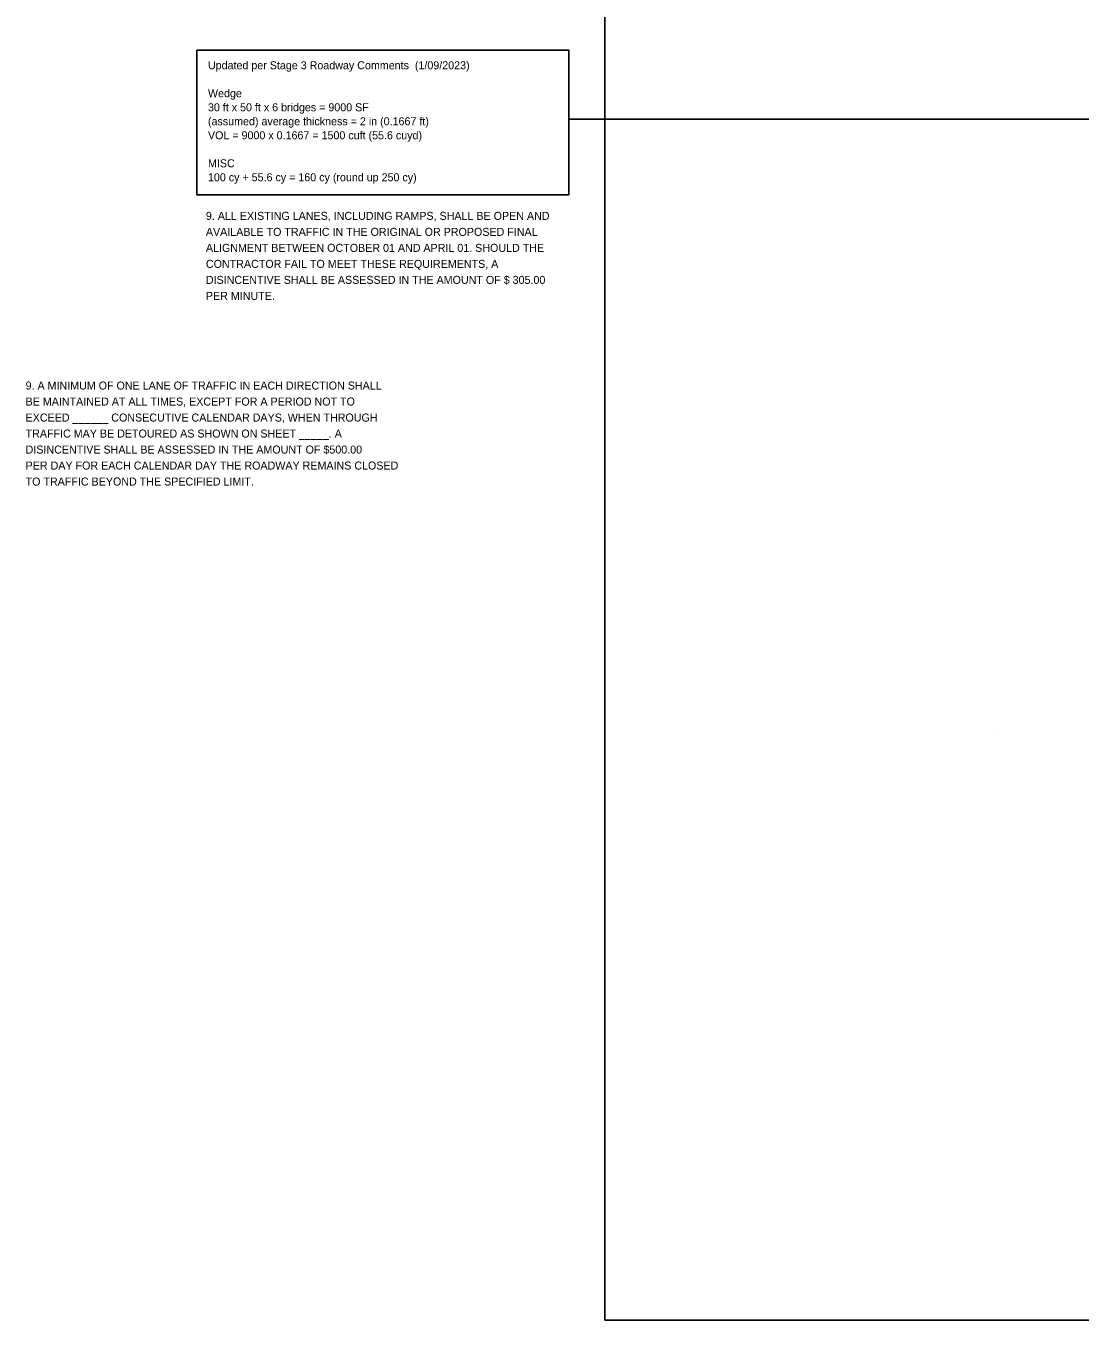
# Model space of a CAD drawing. Extents: x 1820207 to 1820557, y 740216 to 740315.
# Drawn here: x 1820207.07 to 1820225.52, y 740244.01 to 740266.65 of the extents above; entities that cross this region are included whole.
import ezdxf

# ---------------------------------------------------------------- set-up
doc = ezdxf.new("R2010")
doc.units = 0
for name, color, linetype in [('SC_Scratch1', 7, 'Continuous'), ('SC_Shading1', 7, 'Continuous'), ('SH_Text', 7, 'Continuous')]:
    doc.layers.add(name, color=color, linetype=linetype)

msp = doc.modelspace()

# ---------------------------------------------------------------- linework, layer by layer
at = {"layer": 'SC_Scratch1'}
msp.add_line((1820224.047, 740254.242), (1820224.047, 740254.242), dxfattribs=at)
at = {"layer": 'SC_Shading1'}
msp.add_line((1820225.997, 740265.022), (1820216.573, 740265.022), dxfattribs=at)
msp.add_lwpolyline([(1820210.061, 740266.228), (1820216.573, 740266.228), (1820216.573, 740263.7), (1820210.061, 740263.7)], close=True, dxfattribs=at)
at = {"layer": 'SH_Text'}
msp.add_lwpolyline([(1820217.201, 740244.009), (1820515.724, 740244.009), (1820515.724, 740286.62), (1820217.201, 740286.62)], close=True, dxfattribs=at)

# ---------------------------------------------------------------- texts
at = {"layer": 'SC_Shading1'}
for s, p in [('Updated per Stage 3 Roadway Comments  (1/09/2023)', (1820210.257, 740265.895)), ('Wedge', (1820210.257, 740265.405)), ('30 ft x 50 ft x 6 bridges = 9000 SF', (1820210.257, 740265.16)), ('(assumed) average thickness = 2 in (0.1667 ft)', (1820210.257, 740264.915)), ('VOL = 9000 x 0.1667 = 1500 cuft (55.6 cuyd)', (1820210.257, 740264.67)), ('MISC', (1820210.257, 740264.18)), ('100 cy + 55.6 cy = 160 cy (round up 250 cy)', (1820210.257, 740263.935))]:
    msp.add_text(s, height=0.14, dxfattribs=at).set_placement(p)
at = {"layer": 'SH_Text'}
for s, p in [('9. ALL EXISTING LANES, INCLUDING RAMPS, SHALL BE OPEN AND ', (1820210.221, 740263.26)), ('AVAILABLE TO TRAFFIC IN THE ORIGINAL OR PROPOSED FINAL ', (1820210.221, 740262.98)), ('ALIGNMENT BETWEEN OCTOBER 01 AND APRIL 01. SHOULD THE ', (1820210.221, 740262.7)), ('CONTRACTOR FAIL TO MEET THESE REQUIREMENTS, A ', (1820210.221, 740262.42)), ('DISINCENTIVE SHALL BE ASSESSED IN THE AMOUNT OF $ 305.00 ', (1820210.221, 740262.14)), ('PER MINUTE.', (1820210.221, 740261.86)), ('9. A MINIMUM OF ONE LANE OF TRAFFIC IN EACH DIRECTION SHALL ', (1820207.066, 740260.291)), ('BE MAINTAINED AT ALL TIMES, EXCEPT FOR A PERIOD NOT TO ', (1820207.066, 740260.011)), ('EXCEED ______ CONSECUTIVE CALENDAR DAYS, WHEN THROUGH ', (1820207.066, 740259.731)), ('TRAFFIC MAY BE DETOURED AS SHOWN ON SHEET _____. A ', (1820207.066, 740259.451)), ('DISINCENTIVE SHALL BE ASSESSED IN THE AMOUNT OF $500.00 ', (1820207.066, 740259.171)), ('PER DAY FOR EACH CALENDAR DAY THE ROADWAY REMAINS CLOSED ', (1820207.066, 740258.891)), ('TO TRAFFIC BEYOND THE SPECIFIED LIMIT.', (1820207.066, 740258.611))]:
    msp.add_text(s, height=0.14, dxfattribs=at).set_placement(p)

doc.saveas('drawing.dxf')
